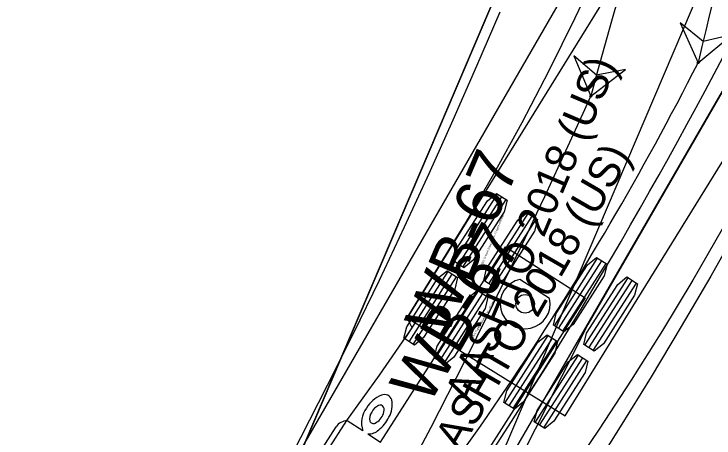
# Model space of a CAD drawing. Extents: x 973688 to 979179, y 703586 to 707602.
# Drawn here: x 973947.11 to 973979.12, y 707251.69 to 707271.07 of the extents above; entities that cross this region are included whole.
import ezdxf

# ---------------------------------------------------------------- set-up
doc = ezdxf.new("R2010")
doc.units = 0
doc.layers.add('0-NPLT', color=7, linetype='Continuous')
doc.layers.add('NO PLOT', color=7, linetype='Continuous')

msp = doc.modelspace()

# ---------------------------------------------------------------- linework, layer by layer
at = {"layer": '0-NPLT'}
for p, q in [((973967.25, 707259.75), (973969.227, 707262.837)), ((973967.25, 707259.75), (973969.227, 707262.837)), ((973967.443, 707259.626), (973969.42, 707262.714)), ((973967.443, 707259.626), (973969.42, 707262.714)), ((973967.636, 707259.503), (973969.613, 707262.59)), ((973967.636, 707259.503), (973969.613, 707262.59)), ((973968.639, 707258.86), (973970.617, 707261.948)), ((973968.639, 707258.86), (973970.617, 707261.948)), ((973968.832, 707258.736), (973970.81, 707261.824)), ((973968.832, 707258.736), (973970.81, 707261.824)), ((973969.025, 707258.613), (973971.003, 707261.7)), ((973969.025, 707258.613), (973971.003, 707261.7)), ((973971.825, 707256.819), (973973.803, 707259.907)), ((973971.825, 707256.819), (973973.803, 707259.907)), ((973972.018, 707256.696), (973973.995, 707259.783)), ((973972.018, 707256.696), (973973.995, 707259.783)), ((973972.211, 707256.572), (973974.188, 707259.66)), ((973972.211, 707256.572), (973974.188, 707259.66)), ((973964.984, 707256.213), (973966.962, 707259.301)), ((973964.984, 707256.213), (973966.962, 707259.301)), ((973965.177, 707256.089), (973967.155, 707259.177)), ((973965.177, 707256.089), (973967.155, 707259.177)), ((973965.37, 707255.966), (973967.348, 707259.053)), ((973965.37, 707255.966), (973967.348, 707259.053)), ((973971.604, 707258.067), (973970.243, 707258.939)), ((973971.604, 707258.067), (973970.243, 707258.939)), ((973973.214, 707255.929), (973975.192, 707259.017)), ((973973.214, 707255.929), (973975.192, 707259.017)), ((973973.407, 707255.806), (973975.385, 707258.893)), ((973973.407, 707255.806), (973975.385, 707258.893)), ((973973.6, 707255.682), (973975.578, 707258.77)), ((973973.6, 707255.682), (973975.578, 707258.77)), ((973966.374, 707255.323), (973968.351, 707258.411)), ((973966.374, 707255.323), (973968.351, 707258.411)), ((973966.567, 707255.2), (973968.544, 707258.287)), ((973966.567, 707255.2), (973968.544, 707258.287)), ((973966.76, 707255.076), (973968.737, 707258.164)), ((973966.76, 707255.076), (973968.737, 707258.164)), ((973969.56, 707253.283), (973971.537, 707256.37)), ((973969.56, 707253.283), (973971.537, 707256.37)), ((973969.753, 707253.159), (973971.73, 707256.247)), ((973969.753, 707253.159), (973971.73, 707256.247)), ((973969.946, 707253.035), (973971.923, 707256.123)), ((973969.946, 707253.035), (973971.923, 707256.123)), ((973970.949, 707252.393), (973972.927, 707255.48)), ((973970.949, 707252.393), (973972.927, 707255.48)), ((973971.142, 707252.269), (973973.12, 707255.357)), ((973971.142, 707252.269), (973973.12, 707255.357)), ((973971.335, 707252.145), (973973.313, 707255.233)), ((973971.335, 707252.145), (973973.313, 707255.233))]:
    msp.add_line(p, q, dxfattribs=at)
for points in [[(973992.958, 707302.175), (973992.939, 707302.186), (973992.902, 707302.126), (973989.92, 707297.307), (973965.088, 707257.177), (973968.703, 707254.94), (973972.317, 707252.704), (973997.148, 707292.835), (974000.129, 707297.654), (974000.166, 707297.714), (974000.148, 707297.726)], [(973992.958, 707302.175), (973992.939, 707302.186), (973992.902, 707302.126), (973989.92, 707297.307), (973965.088, 707257.177), (973968.703, 707254.94), (973972.317, 707252.704), (973997.148, 707292.835), (974000.129, 707297.654), (974000.166, 707297.714), (974000.148, 707297.726)], [(973975.594, 707287.013), (973975.574, 707287.021), (973975.546, 707286.956), (973973.323, 707281.743), (973954.816, 707238.332), (973958.725, 707236.666), (973962.635, 707234.999), (973981.142, 707278.41), (973983.364, 707283.624), (973983.391, 707283.689), (973983.371, 707283.697)], [(973975.594, 707287.013), (973975.574, 707287.021), (973975.546, 707286.956), (973973.323, 707281.743), (973954.816, 707238.332), (973958.725, 707236.666), (973962.635, 707234.999), (973981.142, 707278.41), (973983.364, 707283.624), (973983.391, 707283.689), (973983.371, 707283.697)], [(973955.568, 707240.095), (973973.993, 707283.317)], [(973955.568, 707240.095), (973973.993, 707283.317)], [(973979.494, 707261.232), (973978.152, 707258.904), (973976.766, 707256.602), (973975.341, 707254.331), (973973.876, 707252.092), (973972.372, 707249.885), (973970.835, 707247.717), (973969.262, 707245.584), (973967.634, 707243.46), (973965.906, 707241.291), (973964.139, 707239.161), (973962.334, 707237.069), (973960.975, 707235.545), (973954.238, 707239.86), (973962.328, 707252.491), (973963.821, 707254.56), (973965.324, 707256.73), (973965.088, 707257.177), (973967.733, 707261.468), (973969.059, 707263.77), (973970.343, 707266.107), (973971.585, 707268.486), (973972.781, 707270.893), (973973.929, 707273.329)], [(973979.494, 707261.232), (973978.152, 707258.904), (973976.766, 707256.602), (973975.341, 707254.331), (973973.876, 707252.092), (973972.372, 707249.885), (973970.835, 707247.717), (973969.262, 707245.584), (973967.634, 707243.46), (973965.906, 707241.291), (973964.139, 707239.161), (973962.334, 707237.069), (973960.975, 707235.545), (973954.238, 707239.86), (973962.328, 707252.491), (973963.821, 707254.56), (973965.324, 707256.73), (973965.088, 707257.177), (973967.733, 707261.468), (973969.059, 707263.77), (973970.343, 707266.107), (973971.585, 707268.486), (973972.781, 707270.893), (973973.929, 707273.329)], [(973978.397, 707268.846), (973979.942, 707270.116), (973978.623, 707269.821), (973977.57, 707270.668), (973978.397, 707268.846)], [(973978.397, 707268.846), (973979.942, 707270.116), (973978.623, 707269.821), (973977.57, 707270.668), (973978.397, 707268.846)], [(973980.298, 707261.413), (973978.974, 707259.089), (973977.622, 707256.778), (973976.243, 707254.478), (973974.835, 707252.19), (973973.399, 707249.915)], [(973980.298, 707261.413), (973978.974, 707259.089), (973977.622, 707256.778), (973976.243, 707254.478), (973974.835, 707252.19), (973973.399, 707249.915)], [(973963.295, 707251.872), (973963.873, 707251.502), (973964.002, 707251.702), (973969.59, 707260.428), (973971.414, 707259.26), (973973.237, 707258.092), (973967.648, 707249.366), (973967.52, 707249.166), (973968.098, 707248.796)], [(973963.295, 707251.872), (973963.873, 707251.502), (973964.002, 707251.702), (973969.59, 707260.428), (973971.414, 707259.26), (973973.237, 707258.092), (973967.648, 707249.366), (973967.52, 707249.166), (973968.098, 707248.796)], [(973962.346, 707252.48), (973963.058, 707252.024)], [(973962.346, 707252.48), (973963.058, 707252.024)], [(973958.486, 707248.733), (973958.532, 707248.807), (973958.532, 707248.809), (973958.393, 707249.181), (973958.392, 707249.184), (973958.456, 707249.284), (973958.458, 707249.284), (973958.925, 707248.679), (973958.869, 707248.592), (973958.568, 707248.767), (973958.566, 707248.767), (973958.524, 707248.699), (973958.523, 707248.698), (973958.523, 707248.697), (973958.514, 707248.66), (973958.514, 707248.66), (973959.05, 707247.836), (973961.841, 707252.195)], [(973958.486, 707248.733), (973958.532, 707248.807), (973958.532, 707248.809), (973958.393, 707249.181), (973958.392, 707249.184), (973958.456, 707249.284), (973958.458, 707249.284), (973958.925, 707248.679), (973958.869, 707248.592), (973958.568, 707248.767), (973958.566, 707248.767), (973958.524, 707248.699), (973958.523, 707248.698), (973958.523, 707248.697), (973958.514, 707248.66), (973958.514, 707248.66), (973959.05, 707247.836), (973961.841, 707252.195)]]:
    msp.add_lwpolyline(points, dxfattribs=at)
for points in [[(973978.397, 707268.846), (973979.942, 707270.116), (973978.623, 707269.821), (973977.57, 707270.668)], [(973978.397, 707268.846), (973979.942, 707270.116), (973978.623, 707269.821), (973977.57, 707270.668)], [(973967.683, 707259.472), (973967.202, 707259.78), (973967.333, 707260.306), (973968.757, 707262.529), (973969.179, 707262.868), (973969.661, 707262.56), (973969.529, 707262.034), (973968.105, 707259.811)], [(973967.683, 707259.472), (973967.202, 707259.78), (973967.333, 707260.306), (973968.757, 707262.529), (973969.179, 707262.868), (973969.661, 707262.56), (973969.529, 707262.034), (973968.105, 707259.811)], [(973969.073, 707258.582), (973968.591, 707258.891), (973968.723, 707259.416), (973970.147, 707261.639), (973970.569, 707261.978), (973971.05, 707261.67), (973970.919, 707261.144), (973969.495, 707258.921)], [(973969.073, 707258.582), (973968.591, 707258.891), (973968.723, 707259.416), (973970.147, 707261.639), (973970.569, 707261.978), (973971.05, 707261.67), (973970.919, 707261.144), (973969.495, 707258.921)], [(973972.259, 707256.541), (973971.777, 707256.85), (973971.909, 707257.375), (973973.333, 707259.598), (973973.755, 707259.938), (973974.236, 707259.629), (973974.105, 707259.104), (973972.681, 707256.881)], [(973972.259, 707256.541), (973971.777, 707256.85), (973971.909, 707257.375), (973973.333, 707259.598), (973973.755, 707259.938), (973974.236, 707259.629), (973974.105, 707259.104), (973972.681, 707256.881)], [(973965.418, 707255.935), (973964.936, 707256.244), (973965.068, 707256.769), (973966.492, 707258.992), (973966.914, 707259.331), (973967.396, 707259.023), (973967.264, 707258.498), (973965.84, 707256.275)], [(973965.418, 707255.935), (973964.936, 707256.244), (973965.068, 707256.769), (973966.492, 707258.992), (973966.914, 707259.331), (973967.396, 707259.023), (973967.264, 707258.498), (973965.84, 707256.275)], [(973973.648, 707255.652), (973973.166, 707255.96), (973973.298, 707256.485), (973974.722, 707258.708), (973975.144, 707259.048), (973975.626, 707258.739), (973975.494, 707258.214), (973974.07, 707255.991)], [(973973.648, 707255.652), (973973.166, 707255.96), (973973.298, 707256.485), (973974.722, 707258.708), (973975.144, 707259.048), (973975.626, 707258.739), (973975.494, 707258.214), (973974.07, 707255.991)], [(973966.808, 707255.045), (973966.326, 707255.354), (973966.458, 707255.879), (973967.882, 707258.102), (973968.303, 707258.441), (973968.785, 707258.133), (973968.653, 707257.608), (973967.23, 707255.385)], [(973966.808, 707255.045), (973966.326, 707255.354), (973966.458, 707255.879), (973967.882, 707258.102), (973968.303, 707258.441), (973968.785, 707258.133), (973968.653, 707257.608), (973967.23, 707255.385)], [(973969.993, 707253.005), (973969.512, 707253.313), (973969.643, 707253.838), (973971.067, 707256.062), (973971.489, 707256.401), (973971.971, 707256.092), (973971.839, 707255.567), (973970.415, 707253.344)], [(973969.993, 707253.005), (973969.512, 707253.313), (973969.643, 707253.838), (973971.067, 707256.062), (973971.489, 707256.401), (973971.971, 707256.092), (973971.839, 707255.567), (973970.415, 707253.344)], [(973971.383, 707252.115), (973970.901, 707252.423), (973971.033, 707252.949), (973972.457, 707255.172), (973972.879, 707255.511), (973973.36, 707255.202), (973973.229, 707254.677), (973971.805, 707252.454)], [(973971.383, 707252.115), (973970.901, 707252.423), (973971.033, 707252.949), (973972.457, 707255.172), (973972.879, 707255.511), (973973.36, 707255.202), (973973.229, 707254.677), (973971.805, 707252.454)]]:
    msp.add_lwpolyline(points, close=True, dxfattribs=at)
for centre, radius in [((973978.397, 707268.846), 0.0417), ((973978.397, 707268.846), 0.0417), ((973978.397, 707268.846), 0.0417), ((973978.397, 707268.846), 0.0417), ((973970.485, 707257.822), 0.424), ((973970.485, 707257.822), 0.424)]:
    msp.add_circle(centre, radius, dxfattribs=at)
for centre, radius, start, end in [((974170.093, 707224.287), 196.807, 152.83657, 166.91405), ((974170.093, 707224.287), 196.807, 152.83657, 166.91405), ((974185.202, 707074.23), 266.14, 130.08412, 142.42531), ((974185.202, 707074.23), 266.14, 130.08412, 142.42531), ((973771.826, 707378.695), 234.852, 318.71735, 332.40041), ((973771.826, 707378.695), 234.852, 318.71735, 332.40041), ((973854.978, 707331.503), 138.412, 319.20539, 333.08446), ((973854.978, 707331.503), 138.412, 319.20539, 333.08446), ((973970.487, 707257.823), 1.143, 102.3604, 12.3604), ((973970.487, 707257.823), 1.143, 102.3604, 12.3604), ((973964.055, 707253.328), 0.346, 16.9546, 113.9677), ((973964.055, 707253.328), 0.346, 16.9546, 113.9677), ((973964.453, 707252.334), 1.416, 112.3644, 149.4322), ((973964.453, 707252.334), 1.416, 112.3644, 149.4322), ((973963.273, 707253.2), 1.136, 330.0757, 11.5964), ((973963.273, 707253.2), 1.136, 330.0757, 11.5964), ((973964.14, 707252.37), 1.136, 142.9391, 197.7304), ((973964.14, 707252.37), 1.136, 142.9391, 197.7304), ((973964.055, 707252.564), 0.664, 114.2348, 152.4565), ((973964.055, 707252.564), 0.664, 114.2348, 152.4565), ((973963.86, 707253.017), 0.172, 29.9082, 117.0588), ((973963.86, 707253.017), 0.172, 29.9082, 117.0588), ((973963.676, 707252.961), 0.362, 334.0228, 23.0638), ((973963.676, 707252.961), 0.362, 334.0228, 23.0638), ((973963.895, 707252.573), 0.522, 145.1909, 192.355), ((973963.895, 707252.573), 0.522, 145.1909, 192.355), ((973963.305, 707253.026), 0.732, 295.9521, 342.1865), ((973963.305, 707253.026), 0.732, 295.9521, 342.1865), ((973962.363, 707251.861), 0.619, 91.5207, 147.3624), ((973962.363, 707251.861), 0.619, 91.5207, 147.3624), ((973963.544, 707252.516), 0.169, 198.8073, 298.926), ((973963.544, 707252.516), 0.169, 198.8073, 298.926), ((973962.708, 707253.405), 1.73, 308.7352, 333.5337), ((973962.708, 707253.405), 1.73, 308.7352, 333.5337), ((973963.308, 707252.601), 0.729, 269.0379, 311.5519), ((973963.308, 707252.601), 0.729, 269.0379, 311.5519)]:
    msp.add_arc(centre, radius, start, end, dxfattribs=at)
at = {"layer": 'NO PLOT'}
for points in [[(973990.385, 707286.366), (973973.357, 707256.874), (973970.95, 707252.083), (973969.721, 707249.702)], [(973978.433, 707282.63), (973978.414, 707282.64), (973978.379, 707282.579), (973975.542, 707277.673), (973951.926, 707236.816), (973955.605, 707234.689), (973959.285, 707232.562), (973982.901, 707273.419), (973985.736, 707278.326), (973985.772, 707278.387), (973985.753, 707278.398)], [(973958.989, 707249.336), (973960.231, 707251.71), (973961.45, 707254.097), (973962.646, 707256.496), (973963.819, 707258.91), (973964.969, 707261.336), (973966.096, 707263.776), (973967.2, 707266.229), (973968.282, 707268.696), (973969.34, 707271.175)], [(973973.487, 707267.312), (973975.072, 707268.531), (973973.745, 707268.279), (973972.72, 707269.16), (973973.487, 707267.312)]]:
    msp.add_lwpolyline(points, dxfattribs=at)
msp.add_lwpolyline([(973973.487, 707267.312), (973975.072, 707268.531), (973973.745, 707268.279), (973972.72, 707269.16)], close=True, dxfattribs=at)
msp.add_circle((973973.487, 707267.312), 0.0417, dxfattribs=at)
msp.add_circle((973973.487, 707267.312), 0.0417, dxfattribs=at)
for centre, radius, start, end in [((974179.595, 707212.24), 213.339, 144.72191, 165.04007), ((973709.103, 707385.623), 289.648, 325.2551, 335.89167)]:
    msp.add_arc(centre, radius, start, end, dxfattribs=at)

# ---------------------------------------------------------------- texts
at = {"layer": '0-NPLT'}
for s, height, p in [('AASHTO 2018 (US)', 1.41667, (973968.073, 707253.155)), ('AASHTO 2018 (US)', 1.41667, (973968.073, 707253.155)), ('WB-67', 2.125, (973966.878, 707256.222)), ('WB-67', 2.125, (973966.878, 707256.222)), ('(c) 2021 Transoft Solutions, Inc. All rights reserved.', 0.085, (973968.478, 707259.432)), ('(c) 2021 Transoft Solutions, Inc. All rights reserved.', 0.085, (973968.478, 707259.432))]:
    msp.add_text(s, height=height, rotation=66.9106, dxfattribs=at).set_placement(p)
at = {"layer": 'NO PLOT'}
for s, height, p in [('AASHTO 2018 (US)', 1.41667, (973966.877, 707249.929)), ('WB-67', 2.125, (973966.061, 707253.118)), ('(c) 2021 Transoft Solutions, Inc. All rights reserved.', 0.085, (973968.037, 707256.111))]:
    msp.add_text(s, height=height, rotation=59.9716, dxfattribs=at).set_placement(p)

doc.saveas('drawing.dxf')
